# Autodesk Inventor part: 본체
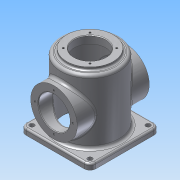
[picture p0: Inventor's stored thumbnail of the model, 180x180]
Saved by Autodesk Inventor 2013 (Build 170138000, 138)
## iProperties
Created: 2015-10
Part Number: 본체
Material: 알루미늄 6061
Document SubType Name: Modeling
Designer: Administrator
Density: 2.71 g/cm^3
Mass: 985.996 g
Surface Area: 1037.34 cm^2
Volume: 363.836 cm^3
Author: Administrator
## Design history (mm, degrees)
sketch "스케치1"
  geometry: C1 r 50 at (0, 0); 1 further point
  constraints: 1 centre point, 1 coincident
  dimensions: "d0" = 100 diameter of C1
extrude "돌출1" new body sketch "스케치1" stored distance "d2" = 110; taper "d3" = 0 deg
sketch "스케치2"
  geometry: L1 (-50, 60)-(50, 60); L2 (60, 50)-(60, -50); L3 (50, -60)-(-50, -60); L4 (-60, -50)-(-60, 50); A1 r 10 centre (-50, 50) between (-50, 60) and (-60, 50); A2 r 10 centre (-50, -50) between (-60, -50) and (-50, -60); A3 r 10 centre (50, -50) between (50, -60) and (60, -50); A4 r 10 centre (50, 50) between (60, 50) and (50, 60); 6 further points
  constraints: 8 end point, 8 point on circle, 8 tangent, 6 point on line, 4 centre point, 3 equal radius, 2 midpoint, 2 parallel, 1 horizontal, 1 horizontal alignment, 1 perpendicular, 1 vertical alignment
  dimensions: "d4" = 120 distance of point (60, 60) point (60, -60); "d6" = 120 distance of point (-60, 60) point (60, 60); "d7" = 10 radius of A1
extrude "돌출2" join sketch "스케치2" distance "d8" = 10; taper "d9" = 0 deg
sketch "스케치3"
  geometry: C1 r 40 at (0, 0); 1 further point
  constraints: 1 centre point, 1 coincident
  dimensions: "d10" = 80 diameter of C1
extrude "돌출3" join sketch "스케치3" distance "d12" = 5; taper "d13" = 0 deg
sketch "스케치5"
  geometry: L1 (-3.318, -19.887)-(-3.318, 29.887); L2 (-3.318, 29.887)-(3.886, 29.887); L3 (3.886, 29.887)-(3.886, -19.887); L4 (3.886, -19.887)-(-3.318, -19.887); L5 (-50, -65)-(50, -65) reference; 4 further points
  constraints: 2 midpoint, 1 horizontal alignment, 1 parallel, 1 vertical alignment, 2 other
  dimensions: "d18" = 70 distance from line of L5 point (0.284, 5); "d19" = 94.88738 distance between parallel lines of L2 L5; "d20" = 7.20489 distance between parallel lines of L3 L1; "d21" = 46.11352 distance from line of L5.end L3
feature "엠보싱1" sketch "스케치5" dims "d22" = 0.5, "d23" = 0
sketch "스케치9"
  geometry: L1 (-50, -65)-(50, -65) reference; C1 r 40 at (0, -5); 1 further point
  constraints: 1 centre point, 1 vertical alignment
  dimensions: "d51" = 60 distance from line of L1 C1.centre; "d52" = 80 diameter of C1
extrude "돌출5" join sketch "스케치9" stored distance "d53" = 124; taper "d54" = 0 deg
sketch "스케치6"
  geometry: L1 (-60, -50)-(-60, 50) reference; L2 (-50, 60)-(50, 60) reference; L3 (60, 50)-(60, -50) reference; L4 (50, -60)-(-50, -60) reference; 5 further points
  constraints: 2 horizontal alignment, 2 vertical alignment
  dimensions: "d24" = 10 distance from line of point (-50, 50) L2; "d25" = 10 distance from line of L1 point (-50, 50); "d26" = 10 distance from line of L4 point (50, -50); "d27" = 10 distance from line of L3 point (50, -50)
hole "구멍1" sketch "스케치6" at (-50, 50), (50, 50), (50, -50), (-50, -50) diameter "d28" = 8; stored, may be unused: countersink angle "d32" = 90 deg, drill point angle "d34" = 118 deg; dims "d29" = 6, "d30" = 4, "d31" = 2, "d33" = 8
sketch "스케치7"
  geometry: 2 further points
  constraints: 1 coincident
hole "구멍2" sketch "스케치7" at (0, 0) diameter "d35" = 54; stored, may be unused: countersink angle "d39" = 90 deg, drill point angle "d41" = 118 deg; dims "d36" = 6, "d37" = 90, "d38" = 112, "d40" = 8
hole "구멍4" diameter "d57" = 54; stored, may be unused: countersink angle "d61" = 90 deg, drill point angle "d63" = 118 deg; dims "d55" = 10, "d56" = 10, "d58" = 6, "d59" = 90, "d60" = 112, "d62" = 8
sketch "스케치10"
  geometry: L1 (-50, 60)-(50, 60) reference; 2 further points
  dimensions: "d64" = 32.5 horizontal distance of point (0, -5) point (-32.5, 0); "d65" = 60 distance from line of L1 point (-32.5, 0)
hole "구멍5" sketch "스케치10" at (-32.5, 0) diameter "d66" = 3.242; stored, may be unused: countersink angle "d70" = 90 deg, drill point angle "d72" = 118 deg; dims "d67" = 8, "d68" = 90, "d69" = 112, "d71" = 10
sketch "스케치11" dims "d77" = 65
  geometry: L1 (-50, 0)-(50, 0); L2 (0, 0)-(35.355, 35.355); L3 (0, 0)-(35.355, -35.355); A1 r 50 centre (0, 0) between (-50, 0) and (50, 0) reference; 4 further points
  constraints: 6 end point, 4 point on circle, 2 coincident, 1 horizontal, 1 midpoint, 1 perpendicular, 1 point on line, 3 other
  dimensions: "d76" = 45 deg angle of L1 L2
hole "구멍6" sketch "스케치11" at (22.981, 22.981) diameter "d79" = 3.242; stored, may be unused: countersink angle "d83" = 90 deg, drill point angle "d85" = 118 deg; dims "d80" = 8, "d81" = 4, "d82" = 2, "d84" = 10
chamfer "모따기1" distance "d89" = 1; stored, may be unused: second distance "d90" = 2, angle "d91" = 45 deg
chamfer "모따기2" distance "d92" = 3; stored, may be unused: second distance "d93" = 2, angle "d94" = 45 deg
chamfer "모따기3" distance "d95" = 1; stored, may be unused: second distance "d96" = 2, angle "d97" = 45 deg
fillet "모깎기1" dims "d98" = 5
fillet "모깎기2" dims "d99" = 5
fillet "모깎기3" dims "d100" = 5
fillet "모깎기4" dims "d101" = 3
fillet "모깎기5" dims "d102" = 3
fillet "모깎기6" dims "d103" = 3
fillet "모깎기7" dims "d104" = 3
sketch "스케치12"
  geometry: C1 r 40 at (0, 0) reference; 1 further point
node "솔리드1"
pattern_circular "원형 패턴1" dims angle "d74" = 360 deg
pattern_circular "원형 패턴2" dims angle "d87" = 360 deg
mirror "대칭1"
